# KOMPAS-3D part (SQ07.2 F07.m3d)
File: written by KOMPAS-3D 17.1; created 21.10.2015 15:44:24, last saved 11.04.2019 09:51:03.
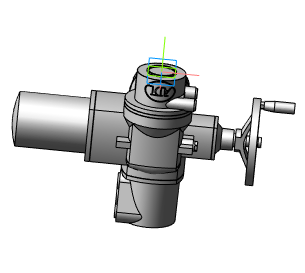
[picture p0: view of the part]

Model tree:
1. Операция без истории:4  (labels: Сталь 20  ГОСТ 1050-88)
